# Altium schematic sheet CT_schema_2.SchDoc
size 271 x 273 mm
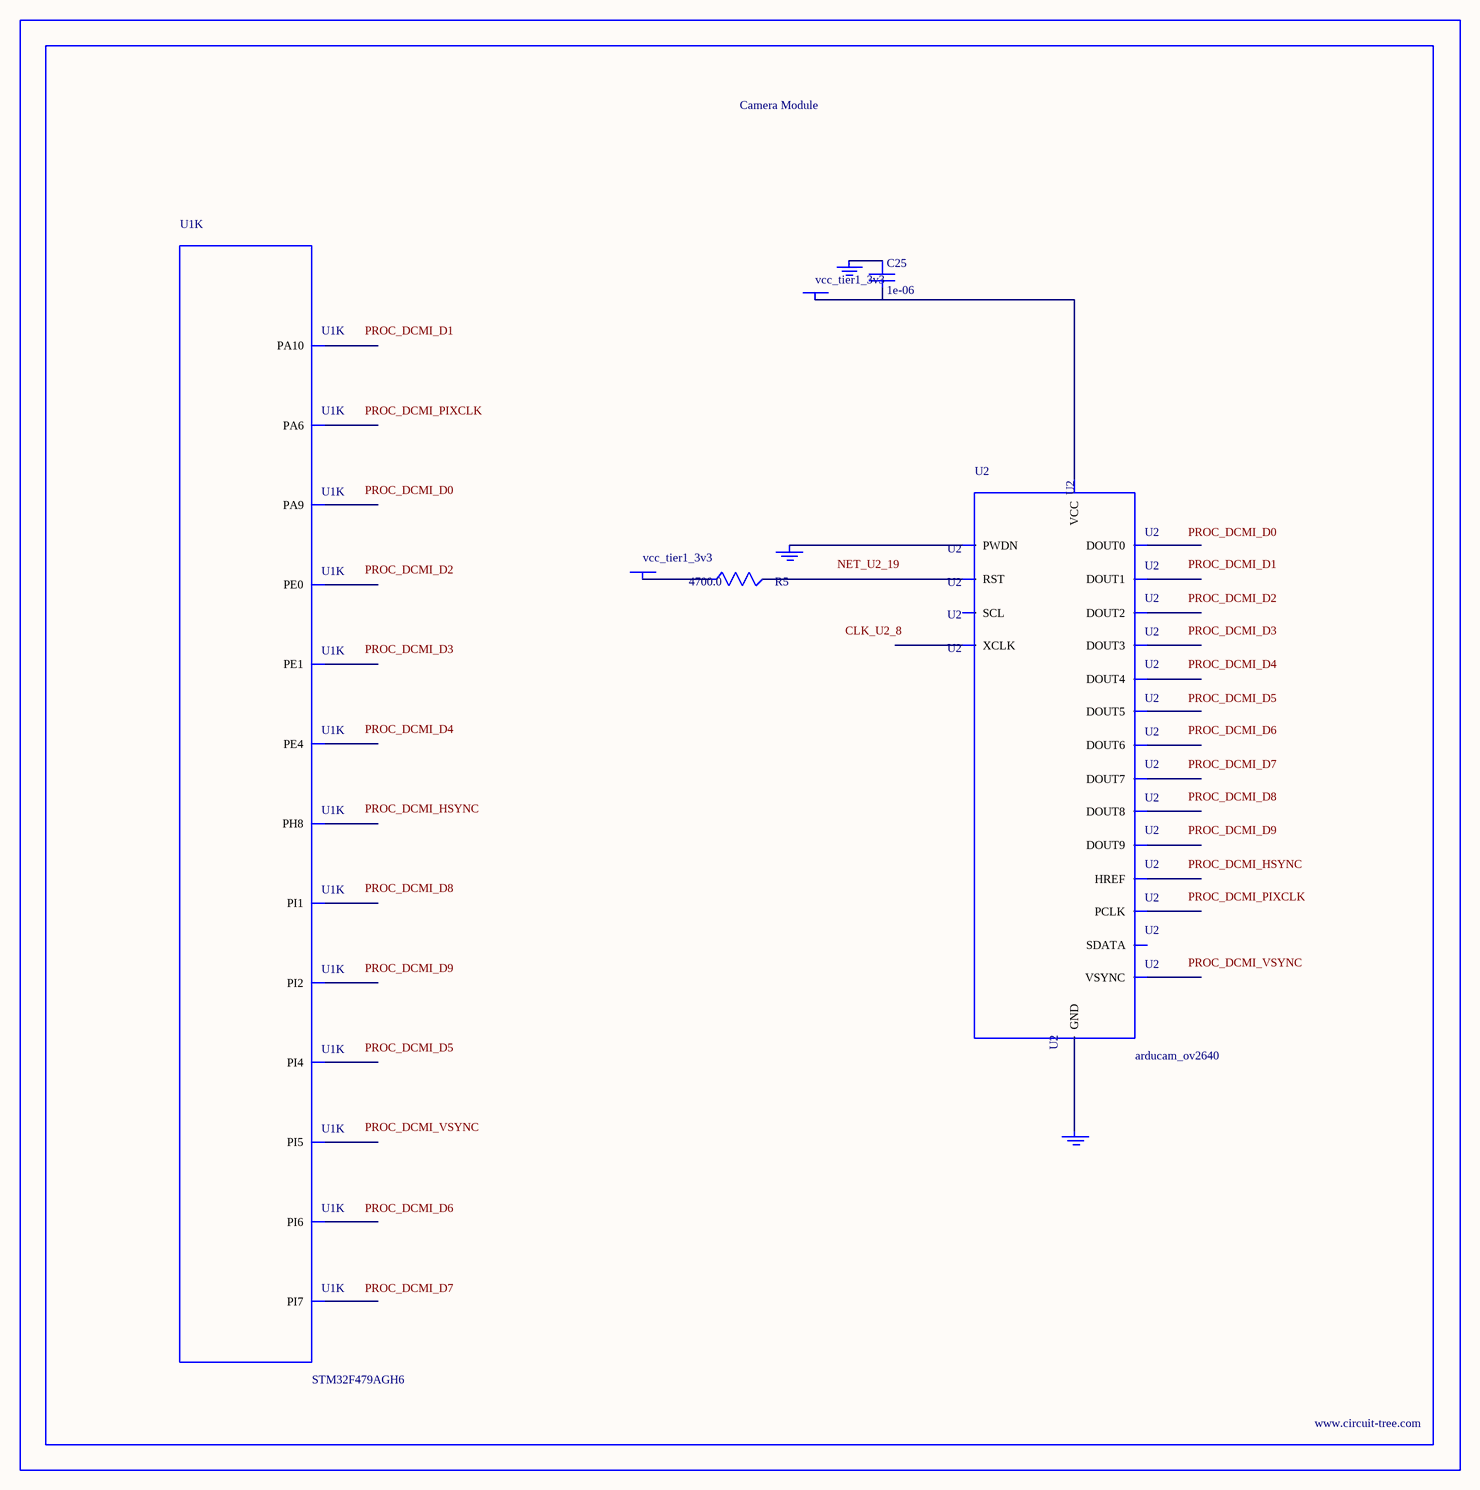
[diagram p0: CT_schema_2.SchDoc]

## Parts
BORDER1  (no value)
C25  1e-06  [C0603]
GND_INSTANCE_1_0  (no value)
GND_INSTANCE_1_1  (no value)
GND_INSTANCE_1_2  (no value)
POWER_INSTANCE_1_0  vcc_tier1_3v3
POWER_INSTANCE_1_1  vcc_tier1_3v3
R5  4700.0  [R0603]
U1  STM32F479AGH6  [UFBGA169]  (part K of 12)
U2  arducam_ov2640  [ARDUCAM]

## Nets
NetC25_1: C25.1 GND_INSTANCE_1_0.0(GND)
NetC25_2: C25.2 POWER_INSTANCE_1_0.0(PWR) U2.1(VCC)
NetGND_INSTANCE_1_1_0: GND_INSTANCE_1_1.0(GND) U2.20(PWDN)
NetGND_INSTANCE_1_2_0: GND_INSTANCE_1_2.0(GND) U2.2(GND)
NetPOWER_INSTANCE_1_1_0: POWER_INSTANCE_1_1.0(PWR) R5.1
NetR5_2: R5.2 U2.19(RST)

Not connected (* = marked no-connect by the designer): U1 A1(PI6) A2(PI5) A3(PE1) A4(PE0) B1(PI7) B3(PI4) B12(PI2) C2(PE4) C11(PI1) E8(PA9) E9(PA10) H8(PH8) N3(PA6); U2 3(SCL) 4(SDATA) 5(VSYNC) 6(HREF) 7(PCLK) 8(XCLK) 9(DOUT9) 10(DOUT8) 11(DOUT7) 12(DOUT6) 13(DOUT5) 14(DOUT4) 15(DOUT3) 16(DOUT2) 17(DOUT1) 18(DOUT0)

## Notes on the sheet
- Labels drawn without touching a wire or pin: CLK_U2_8, NET_U2_19, PROC_DCMI_D0, PROC_DCMI_D1, PROC_DCMI_D2, PROC_DCMI_D3, PROC_DCMI_D4, PROC_DCMI_D5, PROC_DCMI_D6, PROC_DCMI_D7, PROC_DCMI_D8, PROC_DCMI_D9, PROC_DCMI_HSYNC, PROC_DCMI_PIXCLK, PROC_DCMI_VSYNC

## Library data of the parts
BORDER1 = BORDER_PAGE1
C25 = C0603C105K3RACTU
GND_INSTANCE_1_0-GND_INSTANCE_1_2 = GND
POWER_INSTANCE_1_0 POWER_INSTANCE_1_1 = PWR
R5 = RC0603JR-074K7L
